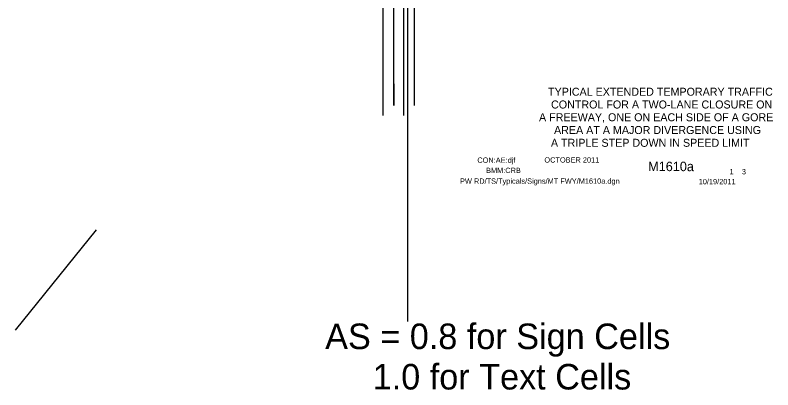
# Model space of a CAD drawing. Extents: x 16554 to 19508, y 5694 to 7079.
# Drawn here: x 16554 to 17434, y 5694 to 6130 of the extents above; entities that cross this region are included whole.
import ezdxf

# ---------------------------------------------------------------- set-up
doc = ezdxf.new("R2010")
doc.units = 0
for name, color, linetype in [('ALI_LEGAL_EX', 7, 'Continuous'), ('BORDER', 7, 'Continuous'), ('BORDER_SIGNAL_WO', 7, 'Continuous'), ('TYPICAL_TEXT_DIMEN_PR', 7, 'Continuous')]:
    doc.layers.add(name, color=color, linetype=linetype)

msp = doc.modelspace()

# ---------------------------------------------------------------- linework, layer by layer
at = {"layer": 'ALI_LEGAL_EX'}
for p, q in [((16980.68, 6877.04), (16980.68, 6013.12)), ((17004.68, 6877.04), (17004.68, 6013.12)), ((16993.65, 6024.8), (16993.65, 6525.15)), ((17017.65, 6024.8), (17017.65, 6525.15)), ((17009.75, 5773.57), (17009.75, 6383.76))]:
    msp.add_line(p, q, dxfattribs=at)
msp.add_lwpolyline([(16993.65, 6049.8), (16993.65, 6024.8)], dxfattribs=at)
at = {"layer": 'TYPICAL_TEXT_DIMEN_PR'}
msp.add_line((16647.75, 5880), (16553.57, 5763.24), dxfattribs=at)

# ---------------------------------------------------------------- texts
at = {"layer": 'BORDER'}
for s, p in [('TYPICAL EXTENDED TEMPORARY TRAFFIC', (17172.85, 6036.12)), ('CONTROL FOR A TWO-LANE CLOSURE ON', (17176.35, 6021.27)), ('A FREEWAY, ONE ON EACH SIDE OF A GORE', (17162.37, 6006.42)), ('AREA AT A MAJOR DIVERGENCE USING', (17179.84, 5991.57)), ('A TRIPLE STEP DOWN IN SPEED LIMIT', (17176.22, 5976.72))]:
    msp.add_text(s, height=9.3, dxfattribs=at).set_placement(p)
at = {"layer": 'BORDER_SIGNAL_WO'}
for s, height, p in [('CON:AE:djf  ', 6.2, (17090.69, 5958.06)), ('    OCTOBER 2011    ', 6.2, (17159.08, 5958.34)), ('BMM:CRB   ', 6.2, (17100.81, 5946.17)), ('    M1610a   ', 11, (17272.86, 5948.38)), (' 1    3 ', 6.2, (17381.45, 5944.7)), ('PW RD/TS/Typicals/Signs/MT FWY/M1610a.dgn      ', 6.2, (17070.55, 5933.71)), ('10/19/2011    ', 6.2, (17347.93, 5933.13)), ('AS = 0.8 for Sign Cells', 29.7271, (16913.84, 5741.4)), ('     1.0 for Text Cells', 29.7271, (16913.84, 5694.4))]:
    msp.add_text(s, height=height, dxfattribs=at).set_placement(p)

doc.saveas('drawing.dxf')
